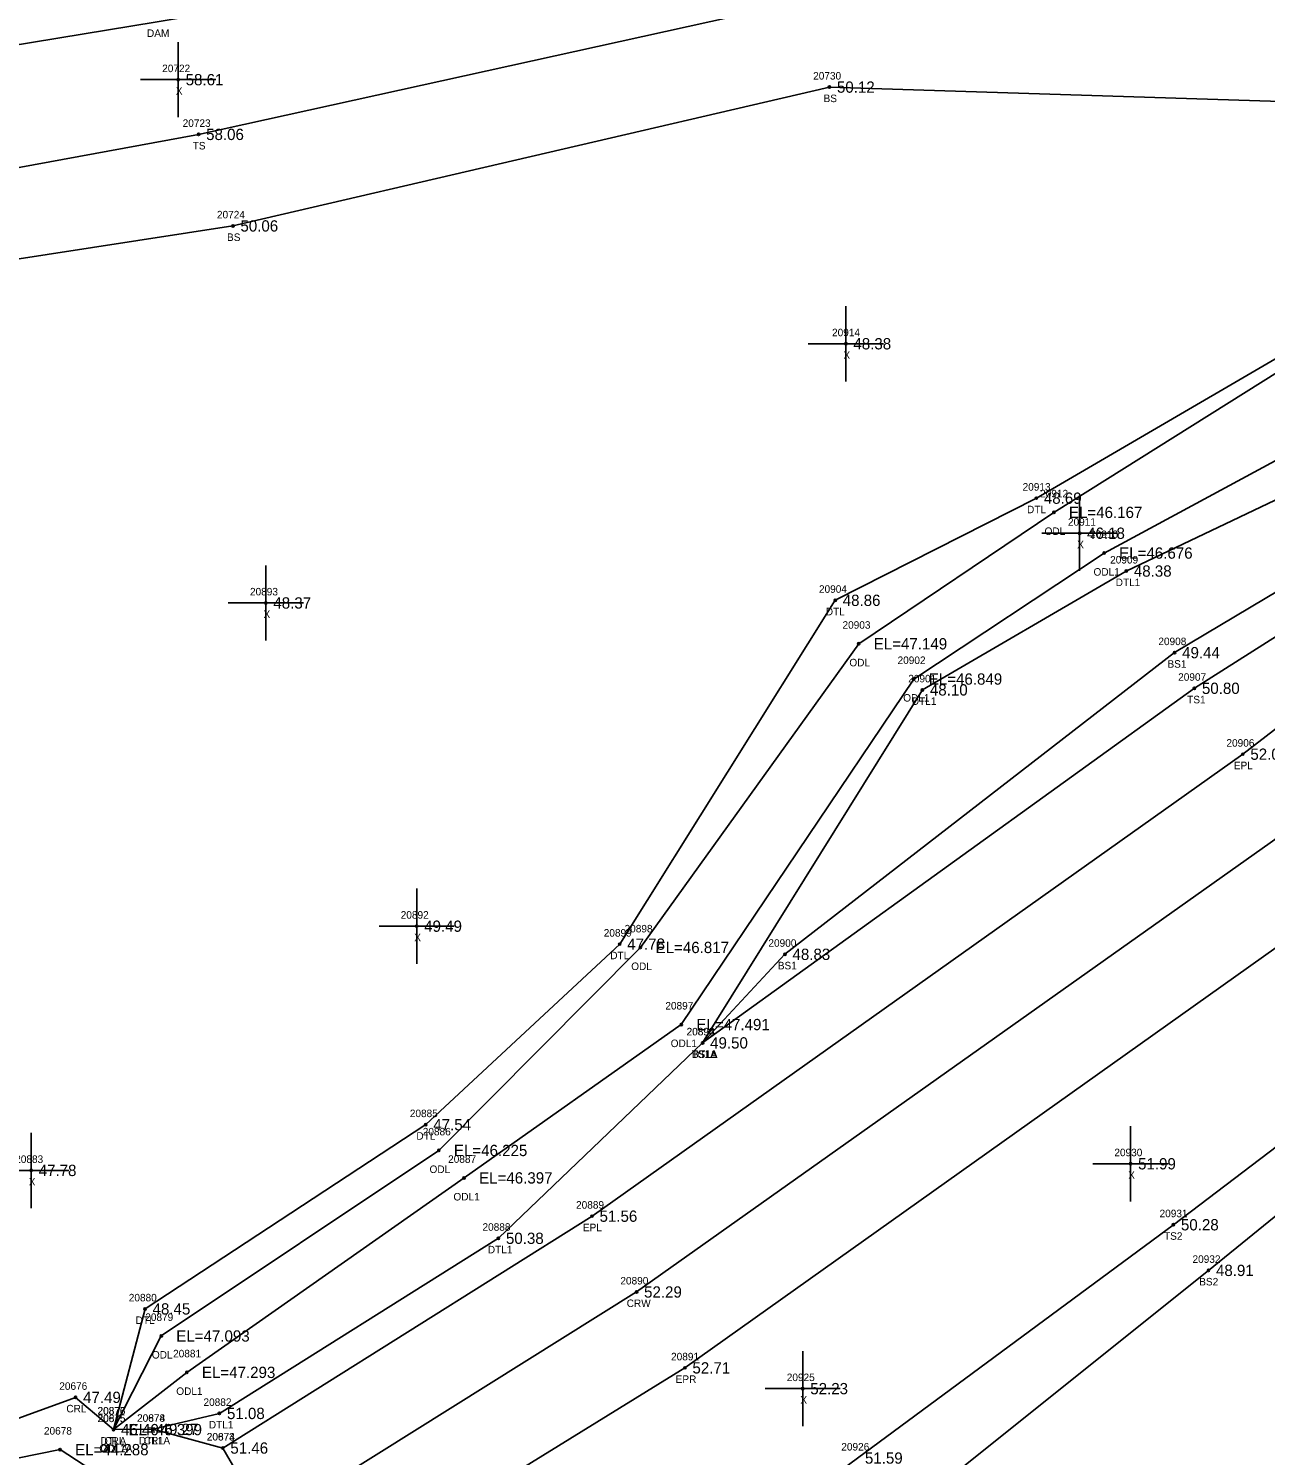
# Model space of a CAD drawing. Extents: x 2420351 to 2422725, y 845330 to 846558.
# Drawn here: x 2421778.1 to 2421942.5, y 845841.9 to 846031.6 of the extents above; entities that cross this region are included whole.
import ezdxf

# ---------------------------------------------------------------- set-up
doc = ezdxf.new("R2010")
doc.units = 0
for name, color, linetype in [('RD_DTM_BkLn1', 7, 'Continuous'), ('RD_DTM_BkLn2', 7, 'Continuous'), ('RD_DTM_BkLn_txCode', 7, 'Continuous'), ('RD_EX_Dam', 7, 'Continuous'), ('RD_EX_Dam_txCode', 7, 'Continuous'), ('RD_EX_H2O', 7, 'Continuous'), ('RD_EX_H2O_txCode', 7, 'Continuous'), ('RD_EX_Misc', 7, 'Continuous'), ('RD_EX_Misc_txCode', 7, 'Continuous'), ('RD_EX_Road', 7, 'Continuous'), ('RD_EX_Road_txCode', 7, 'Continuous'), ('RD_EX_TX_H2O_ELEV', 7, 'Continuous'), ('RD_EX_TX_Misc_ELEV', 7, 'Continuous'), ('RD_EX_TX_Road_ELEV', 7, 'Continuous'), ('RD_HC_Survey_ELEV', 7, 'Continuous'), ('RD_HC_Survey_txCode', 7, 'Continuous'), ('RD_SMD_Locator', 7, 'Continuous')]:
    doc.layers.add(name, color=color, linetype=linetype)

msp = doc.modelspace()

# ---------------------------------------------------------------- linework, layer by layer
at = {"layer": 'RD_DTM_BkLn1'}
msp.add_lwpolyline([(2421809.69, 845832.82), (2421858.88, 845863.61), (2421946.63, 845925.83), (2421988.11, 845958.04), (2422060.85, 846015.47), (2422145.87, 846082.37), (2422217.73, 846139.26), (2422291.07, 846197.06), (2422441.76, 846315.63), (2422509.48, 846369.12), (2422585.38, 846428.46), (2422650.19, 846479.15)], dxfattribs=at)
at = {"layer": 'RD_DTM_BkLn2'}
for points in [[(2421703.45, 845999.67), (2421800.66, 846017.53), (2421880.42, 846035.1), (2421923.1, 846041.94), (2421954.1, 846046.17), (2421954.1, 846046.17), (2422030.99, 846060.95), (2422065.43, 846069.36), (2422120.97, 846103.75), (2422145.48, 846129.05), (2422185.42, 846182.09)], [(2421867.66, 845896.73), (2421878.61, 845908.51), (2421930.41, 845948.62), (2421974.68, 845974.99), (2422048.32, 846029.98), (2422081.44, 846056.32)], [(2421867.66, 845896.73), (2421933.04, 845943.88), (2421976.81, 845971.64), (2422049.15, 846026.28), (2422084.34, 846055.89)], [(2421705.85, 845990.03), (2421805.22, 846005.36), (2421884.52, 846023.82), (2421952.92, 846021.64)], [(2421822.4, 845786.03), (2421837.84, 845804.31), (2421888.24, 845841.53), (2421930.25, 845872.55), (2421966.04, 845899.72), (2422004.21, 845932.1), (2422041.57, 845964.03)], [(2421822.4, 845786.03), (2421841.31, 845799.71), (2421893.73, 845833.52), (2421934.91, 845866.48), (2422007.56, 845925.47), (2422041.57, 845964.03)]]:
    msp.add_lwpolyline(points, dxfattribs=at)
at = {"layer": 'RD_EX_Dam'}
msp.add_lwpolyline([(2421703.45, 845999.67), (2421702.66, 846017.28), (2421795.13, 846032.49), (2421876.44, 846046.05), (2421920.78, 846055.77), (2422010.13, 846069.83), (2422010.13, 846069.83), (2422059.48, 846081.4), (2422106.12, 846132.59), (2422121.56, 846164.68), (2422122.27, 846182.92)], dxfattribs=at)
at = {"layer": 'RD_EX_H2O'}
for points in [[(2421789.64, 845837.83), (2421782.25, 845842.65), (2421762.14, 845838.6), (2421745.54, 845847.69), (2421715.82, 845873.29), (2421690.16, 845897.6), (2421662.52, 845937.52), (2421691.81, 845952.74), (2421695.52, 845998.98), (2421690.3, 846033.46), (2421790.46, 846058.61), (2421873.55, 846071.45), (2421916.6, 846080.01)], [(2421803.88, 845842.86), (2421794.61, 845845.35), (2421789.35, 845845.31), (2421784.3, 845849.6), (2421763.68, 845842.08), (2421749.32, 845850.38), (2421719.73, 845876.64), (2421694.91, 845901.66), (2421677.7, 845939.02), (2421693.6, 845947.01), (2421705.85, 845990.03), (2421703.45, 845999.67)], [(2421789.35, 845845.31), (2421793.54, 845861.36), (2421830.86, 845885.86), (2421856.64, 845909.86), (2421885.29, 845955.58), (2421912.03, 845969.16), (2421958.61, 845996.32), (2421973.32, 845987.17)], [(2421789.35, 845845.31), (2421795.69, 845857.76), (2421832.6, 845882.43), (2421859.41, 845909.42), (2421888.41, 845949.8), (2421914.36, 845967.27), (2421955.72, 845993.22), (2421973.32, 845987.17)], [(2421789.35, 845845.31), (2421799.1, 845852.92), (2421835.95, 845878.78), (2421864.83, 845899.17), (2421895.73, 845945.11), (2421921.04, 845961.86), (2421957.64, 845981.61), (2421973.32, 845987.17)], [(2421794.61, 845845.35), (2421803.43, 845847.46), (2421840.52, 845870.75), (2421867.66, 845896.73), (2421896.88, 845943.67), (2421923.99, 845959.47), (2421960.72, 845976.98), (2421973.32, 845987.17)]]:
    msp.add_lwpolyline(points, dxfattribs=at)
at = {"layer": 'RD_EX_Misc'}
for p, q in [((2421797.94, 846019.81), (2421797.94, 846029.81)), ((2421792.94, 846024.81), (2421802.94, 846024.81)), ((2421886.71, 845984.69), (2421886.71, 845994.69)), ((2421881.71, 845989.69), (2421891.71, 845989.69)), ((2421917.78, 845959.5), (2421917.78, 845969.5)), ((2421912.78, 845964.5), (2421922.78, 845964.5)), ((2421809.6, 845950.23), (2421809.6, 845960.23)), ((2421804.6, 845955.23), (2421814.6, 845955.23)), ((2421829.65, 845907.25), (2421829.65, 845917.25)), ((2421824.65, 845912.25), (2421834.65, 845912.25)), ((2421778.4, 845874.77), (2421778.4, 845884.77)), ((2421924.55, 845875.66), (2421924.55, 845885.66)), ((2421919.55, 845880.66), (2421929.55, 845880.66)), ((2421773.4, 845879.77), (2421783.4, 845879.77)), ((2421880.97, 845845.76), (2421880.97, 845855.76)), ((2421875.97, 845850.76), (2421885.97, 845850.76))]:
    msp.add_line(p, q, dxfattribs=at)
at = {"layer": 'RD_EX_Road'}
for points in [[(2421810.77, 845819.82), (2421809.69, 845832.82), (2421803.88, 845842.86), (2421852.96, 845873.69), (2421939.48, 845935.12), (2421980.78, 845967.01), (2422140.12, 846092.81), (2422210.03, 846148.43), (2422282.88, 846205.21), (2422291.79, 846212.09), (2422354.49, 846261.98), (2422400.82, 846297.88), (2422417.34, 846311.65), (2422435.4, 846324.77), (2422462.49, 846346.77), (2422472.85, 846354.85), (2422502.3, 846378.16), (2422578.05, 846437.54), (2422605.64, 846459.09), (2422626.64, 846476.17), (2422642.61, 846488.86)], [(2421810.77, 845819.82), (2421865.31, 845853.52), (2421953.26, 845916.07), (2421995.06, 845948.03), (2422068.36, 846005.98), (2422153.46, 846073.36), (2422229.55, 846134.03), (2422245.4, 846145.63), (2422297.08, 846186.88), (2422369.77, 846243.69), (2422382.04, 846253.08), (2422449.02, 846305.97), (2422517.14, 846360.1), (2422592.58, 846419.1), (2422657.51, 846470.1)]]:
    msp.add_lwpolyline(points, dxfattribs=at)
at = {"layer": 'RD_SMD_Locator'}
for centre in [(2421797.94, 846024.81), (2421884.52, 846023.82), (2421800.66, 846017.53), (2421805.22, 846005.36), (2421886.71, 845989.69), (2421912.03, 845969.16), (2421914.36, 845967.27), (2421917.78, 845964.5), (2421921.04, 845961.86), (2421923.99, 845959.47), (2421809.6, 845955.23), (2421885.29, 845955.58), (2421888.41, 845949.8), (2421930.41, 845948.62), (2421895.73, 845945.11), (2421896.88, 845943.67), (2421933.04, 845943.88), (2421939.48, 845935.12), (2421829.65, 845912.25), (2421856.64, 845909.86), (2421859.41, 845909.42), (2421878.61, 845908.51), (2421864.83, 845899.17), (2421867.66, 845896.73), (2421867.66, 845896.73), (2421867.66, 845896.73), (2421830.86, 845885.86), (2421832.6, 845882.43), (2421924.55, 845880.66), (2421778.4, 845879.77), (2421835.95, 845878.78), (2421852.96, 845873.69), (2421930.25, 845872.55), (2421840.52, 845870.75), (2421934.91, 845866.48), (2421858.88, 845863.61), (2421793.54, 845861.36), (2421795.69, 845857.76), (2421799.1, 845852.92), (2421865.31, 845853.52), (2421880.97, 845850.76), (2421784.3, 845849.6), (2421803.43, 845847.46), (2421789.35, 845845.31), (2421789.35, 845845.31), (2421789.35, 845845.31), (2421789.35, 845845.31), (2421794.61, 845845.35), (2421794.61, 845845.35), (2421782.25, 845842.65), (2421803.88, 845842.86), (2421803.88, 845842.86)]:
    msp.add_circle(centre, 0.15, dxfattribs=at)

# ---------------------------------------------------------------- texts
at = {"layer": 'RD_DTM_BkLn_txCode'}
for s, p in [('20730', (2421882.36, 846024.82)), ('BS', (2421883.74, 846021.82)), ('20723', (2421798.54, 846018.53)), ('TS', (2421799.87, 846015.53)), ('20724', (2421803.1, 846006.36)), ('BS', (2421804.44, 846003.36)), ('20908', (2421928.25, 845949.62)), ('BS1', (2421929.46, 845946.62)), ('20907', (2421930.88, 845944.88)), ('TS1', (2421932.08, 845941.88)), ('20900', (2421876.41, 845909.51)), ('BS1', (2421877.66, 845906.51)), ('20896', (2421865.52, 845897.73)), ('20895', (2421865.54, 845897.73)), ('TS1A', (2421866.21, 845894.73)), ('BS1A', (2421866.23, 845894.73)), ('20931', (2421928.41, 845873.55)), ('TS2', (2421929, 845870.55)), ('20932', (2421932.79, 845867.48)), ('BS2', (2421933.68, 845864.48)), ('20926', (2421886.1, 845842.53))]:
    msp.add_text(s, height=1, dxfattribs=at).set_placement(p)
at = {"layer": 'RD_EX_Dam_txCode'}
msp.add_text('DAM', height=1, dxfattribs=at).set_placement((2421793.8, 846030.49))
at = {"layer": 'RD_EX_H2O_txCode'}
for s, p in [('20913', (2421910.2, 845970.16)), ('20912', (2421912.53, 845969.27)), ('DTL', (2421910.79, 845967.16)), ('ODL', (2421913.12, 845964.27)), ('20910', (2421919.17, 845963.86)), ('20909', (2421921.84, 845960.47)), ('ODL1', (2421919.63, 845958.86)), ('DTL1', (2421922.58, 845957.47)), ('20904', (2421883.13, 845956.58)), ('DTL', (2421884.04, 845953.58)), ('20903', (2421886.26, 845951.8)), ('ODL', (2421887.17, 845946.8)), ('20902', (2421893.58, 845947.11)), ('20901', (2421895, 845944.67)), ('ODL1', (2421894.33, 845942.11)), ('DTL1', (2421895.47, 845941.67)), ('20899', (2421854.52, 845910.86)), ('20898', (2421857.29, 845911.42)), ('DTL', (2421855.39, 845907.86)), ('ODL', (2421858.17, 845906.42)), ('20897', (2421862.71, 845901.17)), ('20894', (2421865.54, 845897.73)), ('ODL1', (2421863.42, 845896.17)), ('DTL1', (2421866.25, 845894.73)), ('20885', (2421828.74, 845886.86)), ('DTL', (2421829.61, 845883.86)), ('20886', (2421830.46, 845884.43)), ('ODL', (2421831.36, 845879.43)), ('20887', (2421833.83, 845880.78)), ('ODL1', (2421834.54, 845875.78)), ('20888', (2421838.4, 845871.75)), ('DTL1', (2421839.11, 845868.75)), ('20880', (2421791.38, 845862.36)), ('DTL', (2421792.29, 845859.36)), ('20879', (2421793.57, 845859.76)), ('ODL', (2421794.45, 845854.76)), ('20881', (2421797.27, 845854.92)), ('20676', (2421782.14, 845850.6)), ('ODL1', (2421797.69, 845849.92)), ('CRL', (2421783.08, 845847.6)), ('20876', (2421787.21, 845847.31)), ('20877', (2421787.24, 845847.31)), ('20882', (2421801.31, 845848.46)), ('20675', (2421787.21, 845846.31)), ('20875', (2421787.24, 845846.31)), ('20674', (2421792.47, 845846.35)), ('20878', (2421792.49, 845846.35)), ('DTL1', (2421802.02, 845845.46)), ('20678', (2421780.1, 845844.65)), ('DTLA', (2421787.62, 845843.31)), ('CRL', (2421788.13, 845843.31)), ('DTL1A', (2421792.71, 845843.35)), ('CRL', (2421793.38, 845843.35)), ('20673', (2421801.74, 845843.86)), ('ODL1A', (2421787.46, 845842.31)), ('ODLA', (2421787.62, 845842.31))]:
    msp.add_text(s, height=1, dxfattribs=at).set_placement(p)
at = {"layer": 'RD_EX_Misc_txCode'}
for s, p in [('20722', (2421795.82, 846025.81)), ('X', (2421797.63, 846022.81)), ('20914', (2421884.87, 845990.69)), ('X', (2421886.39, 845987.69)), ('20911', (2421916.23, 845965.5)), ('X', (2421917.46, 845962.5)), ('20893', (2421807.49, 845956.23)), ('X', (2421809.29, 845953.23)), ('20892', (2421827.53, 845913.25)), ('X', (2421829.33, 845910.25)), ('20930', (2421922.4, 845881.66)), ('20883', (2421776.28, 845880.77)), ('X', (2421778.08, 845877.77)), ('X', (2421924.24, 845878.66)), ('20925', (2421878.85, 845851.76)), ('X', (2421880.66, 845848.76))]:
    msp.add_text(s, height=1, dxfattribs=at).set_placement(p)
at = {"layer": 'RD_EX_Road_txCode'}
for s, p in [('20906', (2421937.3, 845936.12)), ('EPL', (2421938.28, 845933.12)), ('20889', (2421850.84, 845874.69)), ('EPL', (2421851.75, 845871.69)), ('20891', (2421863.47, 845854.52)), ('EPR', (2421864.08, 845851.52)), ('20874', (2421801.76, 845843.86))]:
    msp.add_text(s, height=1, dxfattribs=at).set_placement(p)
at = {"layer": 'RD_EX_TX_H2O_ELEV'}
for s, p in [('48.69', (2421913.03, 845968.41)), ('EL=46.167', (2421916.36, 845966.52)), ('EL=46.676', (2421923.04, 845961.11)), ('48.38', (2421924.99, 845958.72)), ('48.86', (2421886.29, 845954.83)), ('EL=47.149', (2421890.41, 845949.05)), ('EL=46.849', (2421897.73, 845944.36)), ('48.10', (2421897.88, 845942.92)), ('47.78', (2421857.64, 845909.11)), ('EL=46.817', (2421861.41, 845908.67)), ('EL=47.491', (2421866.83, 845898.42)), ('49.50', (2421868.66, 845895.98)), ('47.54', (2421831.86, 845885.11)), ('EL=46.225', (2421834.6, 845881.68)), ('EL=46.397', (2421837.95, 845878.03)), ('50.38', (2421841.52, 845870)), ('48.45', (2421794.54, 845860.61)), ('EL=47.093', (2421797.69, 845857.01)), ('EL=47.293', (2421801.1, 845852.17)), ('47.49', (2421785.3, 845848.85)), ('51.08', (2421804.43, 845846.71)), ('49.27', (2421795.61, 845844.6)), ('49.27', (2421795.61, 845844.6)), ('46.40', (2421790.35, 845844.56)), ('46.40', (2421790.35, 845844.56)), ('EL=46.399', (2421791.35, 845844.56)), ('EL=46.399', (2421791.35, 845844.56)), ('EL=44.288', (2421784.25, 845841.9)), ('51.46', (2421804.88, 845842.11))]:
    msp.add_text(s, height=1.5, dxfattribs=at).set_placement(p)
at = {"layer": 'RD_EX_TX_Misc_ELEV'}
for s, p in [('58.61', (2421798.94, 846024.06)), ('50.12', (2421885.52, 846023.07)), ('58.06', (2421801.66, 846016.78)), ('50.06', (2421806.22, 846004.61)), ('48.38', (2421887.71, 845988.94)), ('46.18', (2421918.78, 845963.75)), ('48.37', (2421810.6, 845954.48)), ('49.44', (2421931.41, 845947.87)), ('50.80', (2421934.04, 845943.13)), ('49.49', (2421830.65, 845911.5)), ('48.83', (2421879.61, 845907.76)), ('49.50', (2421868.66, 845895.98)), ('49.50', (2421868.66, 845895.98)), ('47.78', (2421779.4, 845879.02)), ('51.99', (2421925.55, 845879.91)), ('50.28', (2421931.25, 845871.8)), ('48.91', (2421935.91, 845865.73)), ('52.23', (2421881.97, 845850.01)), ('51.59', (2421889.24, 845840.78))]:
    msp.add_text(s, height=1.5, dxfattribs=at).set_placement(p)
at = {"layer": 'RD_EX_TX_Road_ELEV'}
for s, p in [('52.08', (2421940.48, 845934.37)), ('51.56', (2421853.96, 845872.94)), ('52.71', (2421866.31, 845852.77)), ('51.46', (2421804.88, 845842.11))]:
    msp.add_text(s, height=1.5, dxfattribs=at).set_placement(p)
at = {"layer": 'RD_HC_Survey_ELEV'}
msp.add_text('52.29', height=1.5, dxfattribs=at).set_placement((2421859.88, 845862.86))
at = {"layer": 'RD_HC_Survey_txCode'}
for s, p in [('20890', (2421856.73, 845864.61)), ('CRW', (2421857.57, 845861.61))]:
    msp.add_text(s, height=1, dxfattribs=at).set_placement(p)

doc.saveas('drawing.dxf')
